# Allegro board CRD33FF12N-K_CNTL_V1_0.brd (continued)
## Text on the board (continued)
DIMENSION: Fab Notes: | 1. Fabricate to IPC-6012-II, current revision. | 2. All vias need to be plugged except the vias on pad. | 3. Attention: the thickness of the material's adjustment should be less than 20% for each layer(Core/PP). | For instance: the thickness of Core-1 is 4mil, then the adjustment range will be 3.2-4.8mil. | Board Name : | Dielectric Material : | Surface  Finished : | Soldermask Colors : | Silk Screen Colors : | Outline Profile : | FR4 | Immersion Gold | Green | White | Router | Board Thickness : | Spell   Mode  : | E-TEST Checker : | UL-MAKE : | Gold Finger Plating: | 1.60mm +/- 10% | Yes | No | 2 X 5 | Layers : | Board Cut Out : | Gold Thickness: | UL-MAKE Layer : | 4 | >=0.05um | Silk Top | Purchase Order & Specification Sheet | FAB DRAWING
ASSEMBLY_TOP: PRIMARY SIDE
ASSEMBLY_BOTTOM: SECONDARY SIDE
User.14: FIGURE | SIZE | 10.0 | 40.0 | DRILL CHART: TOP to BOTTOM | ALL UNITS ARE IN MILS | PLATED | QTY | 300 | 40 | 2
